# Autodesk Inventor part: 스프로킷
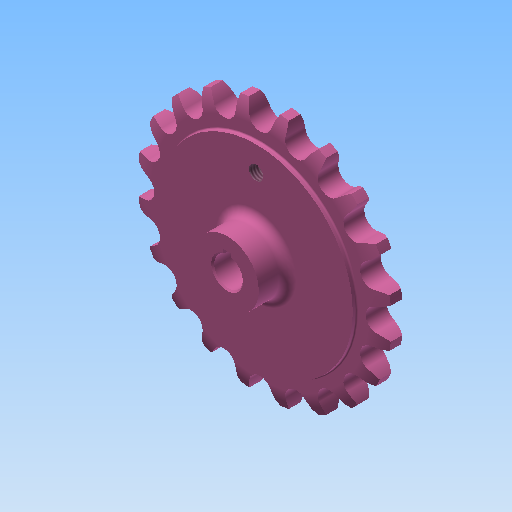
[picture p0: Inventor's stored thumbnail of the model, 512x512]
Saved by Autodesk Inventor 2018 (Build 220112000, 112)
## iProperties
Created: 2016-03
Part Number: 스프로킷
Material: 강철, 탄소
Document SubType Name: Modeling
Designer: mduedu
Density: 7.87 g/cm^3
Mass: 371.373 g
Surface Area: 144.258 cm^2
Volume: 47.1885 cm^3
Appearance: 분홍색
Author: mduedu
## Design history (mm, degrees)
sketch "스케치1"
  geometry: L1 (0, 5)-(33.5, 5); L2 (33.5, 5)-(33.5, 4.1); L3 (34, 3.6)-(37.625, 3.6); L4 (44, 2)-(44, 0); L5 (44, 0)-(0, 0); L6 (0, 0)-(0, 5); L7 (0, -5)-(33.5, -5); L8 (33.5, -5)-(33.5, -4.1); L9 (34, -3.6)-(37.625, -3.6); L10 (44, -2)-(44, 0); L11 (0, 0)-(0, -5); A1 r 13.5 centre (37.625, -9.9) between (44, 2) and (37.625, 3.6); A2 r 13.5 centre (37.625, 9.9) between (37.625, -3.6) and (44, -2); A3 r 0.5 centre (34, 4.1) between (33.5, 4.1) and (34, 3.6); A4 r 0.5 centre (34, -4.1) between (34, -3.6) and (33.5, -4.1); 2 further points
  constraints: 22 end point, 8 point on circle, 6 symmetric about line, 5 tangent, 4 centre point, 4 parallel, 4 point on line, 1 equal radius, 1 horizontal, 1 perpendicular, 1 other
  dimensions: "d0" = 88 diameter of L4 L6; "d2" = 67 diameter of L2 L6; "d3" = 1.6 vertical distance of L4.start L3.end; "d4" = 3.6 distance from line of L4.end L3; "d5" = 5 distance between parallel lines of L5 L1; "d6" = 13.5 radius of A1; "d15" = 0.5 radius of A3
revolve "회전1" sketch "스케치1" stored, may be unused: angle "d7" = 90 deg
sketch "스케치2" dims "d8" = 73.23, "d11" = 88
  geometry: L1 (0, 0)-(0, 36.615); A1 r 40.59 centre (0, 0) between (-16.319, 37.165) and (0, 40.59); A2 r 3.975 centre (0, 40.59) between (-3.89, 39.774) and (0, 36.615); A3 r 12.7 centre (-16.319, 37.165) between (-3.89, 39.774) and (-5.41, 43.666); A4 r 12.7 centre (16.319, 37.165) between (5.41, 43.666) and (3.89, 39.774); A5 r 3.975 centre (0, 40.59) between (0, 36.615) and (3.89, 39.774); A6 r 44 centre (0, 0) between (5.41, 43.666) and (-5.41, 43.666); 2 further points
  constraints: 12 point on circle, 6 centre point, 4 coincident, 3 symmetric about line, 2 end point, 1 point on line, 1 tangent, 1 vertical, 1 vertical alignment, 7 other
  dimensions: "d10" = 81.18 diameter of A1; "d12" = 12.7 radius of A3
extrude "돌출1" cut sketch "스케치2" extent not by distance; stored distance "d13" = 10; taper "d14" = 0 deg
sketch "스케치3"
  geometry: C1 r 11 at (0, 0); 1 further point
  constraints: 1 centre point, 1 coincident
  dimensions: "d19" = 22 diameter of C1
extrude "돌출2" join sketch "스케치3" distance "d20" = 10; taper "d21" = 0 deg
sketch "스케치4"
  geometry: L1 (-1.5, 0)-(1.5, 0); L2 (1.5, 0)-(1.5, 6.4); L3 (1.5, 6.4)-(-1.5, 6.4); L4 (-1.5, 6.4)-(-1.5, 0); C1 r 5 at (0, 0); 2 further points
  constraints: 8 end point, 2 coincident, 2 parallel, 1 centre point, 1 horizontal, 1 midpoint, 1 perpendicular
  dimensions: "d23" = 10 diameter of C1; "d25" = 3 distance of L2.end L3.end; "d26" = 6.4 distance of L1.end L2.end
extrude "돌출3" cut sketch "스케치4" extent not by distance; stored distance "d27" = 8; taper "d28" = 0 deg
fillet "모깎기1" dims "d22" = 3
chamfer "모따기1" distance "d29" = 0.5; stored, may be unused: second distance "d30" = 2, angle "d31" = 45 deg
sketch "스케치6" dims "d46" = 50
  geometry: 3 further points
  constraints: 2 vertical alignment, 1 coincident, 2 other
hole "구멍2" sketch "스케치6" at (0, 25) diameter "d48" = 4.917; stored, may be unused: countersink angle "d52" = 90 deg, drill point angle "d54" = 118 deg; dims "d49" = 6, "d50" = 4, "d51" = 2, "d53" = 8
node "솔리드1"
pattern_circular "원형 패턴1" dims angle "d17" = 360 deg
